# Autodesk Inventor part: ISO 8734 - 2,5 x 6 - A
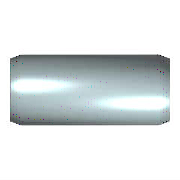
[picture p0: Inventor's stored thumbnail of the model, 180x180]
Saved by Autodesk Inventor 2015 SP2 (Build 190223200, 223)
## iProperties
IsCustomPart: 0
Created: 2012-02
Part Number: ISO 8734 - 2,5 x 6 - A
Material: Stahl
Description: Zylinderstifte aus gehärtetem Martensit-Edelstahl (Passstifte)
Document SubType Name: Modeling
Standard: ISO 8734
Designer: rYan
Standard Revision: Second edition 1997-11-15
Standards Organization: ISO
Language: de-DE
Size Designation: 2,5 x 6 - A
Categories: <MemberInstance><Categories><Category DisplayName="Verbindungselemente" InternalName="e4da775c-781d-43d5-af7c-5136215cf5a6" Mnemonic="FSTN"><Category DisplayNam
Density: 7.85 g/cm^3
Mass: 0.228634 g
Surface Area: 0.552727 cm^2
Volume: 0.0291253 cm^3
Appearance: Platte
Author: rYan
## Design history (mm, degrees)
sketch "Skizze"
  geometry: C1 r 1.25 at (0, 0); 1 further point
  constraints: 1 centre point, 1 coincident
  dimensions: "d1" = 2.5 diameter of C1 (= NND)
extrude "Körper" new body sketch "Skizze" distance "d2" = 6 (= NLG); taper "d3" = 0 deg
chamfer "Skizze2" distance "d8" = 0.4 (= PHH); stored, may be unused: angle "d9" = 15 deg (= FAWI), second distance "d12" = 0.4 (= PHH)
body "Solid1"
chamfer "Fase1" distance "d4" = 0.4 (= PHH); stored, may be unused: angle "d5" = 15 deg (= FAWI), second distance "d11" = 0.4 (= PHH)
other parameters: "NND" = 2.5 [user parameter; used in 1 equation term], "NLG" = 6 [user parameter; used in 1 equation term], "PHH" = 0.4 [user parameter; used in 5 equation terms], "FAWI" = 15 deg [user parameter; used in 2 equation terms], "d13" = 0, "d15" = 0, "d16" = 0, "PHH2" = 0.4 (= PHH) [user parameter], "FAWI2" = 15 deg [user parameter]
